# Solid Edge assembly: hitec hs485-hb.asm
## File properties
Author: nakano
Template: iso metric assembly.asm
Last saved by: nakano
Revision: 5
Application: Solid Edge
Username: nakano
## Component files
hitec HS485-HB.par
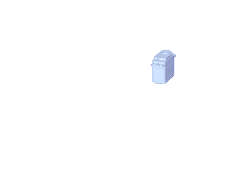
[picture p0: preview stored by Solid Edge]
